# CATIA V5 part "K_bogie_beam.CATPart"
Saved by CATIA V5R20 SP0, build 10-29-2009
Part number: bogie_beam
Publications: "Droite.2", "Plan.3", "Corps principal", "Plan_pivot_bogie_tige", "Demi_bogie_beam"
Bounding box of the stored display mesh (mm): x -40 to 40, y -445.489 to 457.761, z -37.179 to 213.669
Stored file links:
  G:\Khaled_CFAO_2011\ST2M\ST2M_GR2\echouteau\Khaled\CAD_ThinkMotion\K_bogie_beam.CATPart
  F:\2A\Proj Think Motion\trainv3\Version3\sql_general.CATProduct
  G:\Khaled_CFAO_2011\ST2M\ST2M_GR2\echouteau\Khaled\CAD_ThinkMotion\K_tige.CATPart
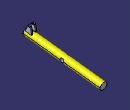
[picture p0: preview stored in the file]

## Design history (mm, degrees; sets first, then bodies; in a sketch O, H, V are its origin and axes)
Parameters
  Demi_bogie_beam = 400 mm
Set1
  Plane1 "plan_ref": linked copy from another document
  Point1: linked copy from another document
Body1 (main body)
  Point2: type OnPlane, Support Plane1, H 0, V 400 {= Demi_bogie_beam}, Direction (1, 0, 0)
  Point3: type OnPlane, Support Plane1, H 0, V -400 {= -Demi_bogie_beam}, Direction (1, 0, 0)
  Line1: type PtPt, FirstPoint Point2, SecondPoint Point3, Support Plane1
  Plane2: type OffsetPt, RefPlane Plane1, RefPoint Point3
  Plane3: type Offset, RefPlane Plane2, Offset 100
  Line2: type PtDir, RefPoint Point3, Direction Plane2, Start 0, End 100
  Plane4: type 1Line1Pt, RefPoint vertex of Line2, Line Line1
  Plane5 "Plan_pivot_bogie_tige": type OffsetPt, RefPlane Plane4, RefPoint Point3
  Plane6 "Plan_pivot_paire_roue": type Normal, Curve Line1, RefPoint Point3
  Line3: type PtDir, RefPoint Point1, Direction yz-plane, Start 0, End -157
  Plane7: type OffsetPt, RefPlane yz-plane, RefPoint vertex of Line3
  Line4: type PtDir, RefPoint vertex of Line2, Direction yz-plane, Start 0, End 150
  Plane8: type OffsetPt, RefPlane yz-plane, RefPoint vertex of Line4
  Line5 "Droite.qs": type Normal, RefPoint Point3, RefSkin Plane5, Start 0, End 250
  Line6 "Droite.qs": type Normal, RefPoint Point2, RefSkin Plane5, Start 0, End 250
  Plane9 "Plan.dec": type Offset, RefPlane Plane6, Offset 50
  Plane10: type OffsetPt, RefPlane Plane6, RefPoint Point2
  Plane11: type Offset, RefPlane Plane10, Offset 50, reversed
  Sketch1 on Plane9, origin (0, -452.9146, 0.1661), H (1, 0, 0), V (0, 0.1136, 0.9935)
    circle A1 centre (0, 105.2996) radius 40
    point P1 (0, 105.2996)
    reference projected point E1 (0, 105.2996) from Point2
    coincidence: P1 E1
  Pad1: profile Sketch1, direction (0, 0.9935, -0.1136), up to Plane11
  Plane12: stored without definition
  Plane13: stored without definition
  Point4: stored without definition
  Sketch2 on Plane13, origin (166, 16.1619, 44.1149), H (0, 1, 0), V (0, 0, 1)
    point P1 (-10.0259, 9.5353)
    reference projected point E1 (-10.0259, 9.5353) from Point4
    coincidence: P1 E1
  Hole1: placed by Sketch2, at (166, 6.136, 53.6503) direction (-1, 0, 0), diameter 45, up to Plane7
  Point5: stored without definition
  Line7: stored without definition
  Sketch3 on Plane9, origin (0, -447.0854, 51.1334), H (1, 0, 0), V (0, 0.1136, 0.9935)
    line L1 (29.6689, 171.2035) -> (29.6689, 80.2774)
    point P1 (29.6689, 171.2035)
    point P2 (29.6689, 80.2774)
    line L2 (29.6689, 80.2774) -> (0, 80.2774)
    point P3 (0, 80.2774)
    line L3 (29.6689, 171.2035) -> (16, 171.2035)
    point P4 (16, 171.2035)
    line L4 (16, 171.2035) -> (16, 92.17)
    point P5 (16, 92.17)
    line L5 (16, 92.17) -> (0, 92.17)
    point P6 (0, 92.17)
    point P7 (0, 80.2774)
    point P8 (-29.6689, 80.2774)
    line L6 (-29.6689, 80.2774) -> (0, 80.2774)
    point P9 (0, 92.17)
    point P10 (-16, 92.17)
    line L7 (-16, 92.17) -> (0, 92.17)
    point P11 (-16, 171.2035)
    line L8 (-16, 171.2035) -> (-16, 92.17)
    point P12 (-29.6689, 171.2035)
    line L9 (-29.6689, 171.2035) -> (-16, 171.2035)
    line L10 (-29.6689, 171.2035) -> (-29.6689, 80.2774)
    length L5 = 16
    vertical: L1 V, L4 V
    coincidence: P3 V, P6 V, P3 P7, P6 P9
    horizontal: L2 H, L3 H, L5 H
    symmetry: P3 P7 V, P2 P8 V, L2 L6 V, P6 P9 V, P5 P10 V, L5 L7 V, P4 P11 V, L4 L8 V, P1 P12 V, L3 L9 V, L1 L10 V
  Sketch4 on Plane5, origin (0, 0, 0), H (0, -1, 0), V (0, 0, 1)
    arc A1 centre (379.9103, 198.4545) radius 15.2266 from (393.8223, 204.6437) to (364.9601, 201.3427) ccw
    point P1 (379.9103, 198.4545)
    reference projected point E1 (379.9103, 198.4545) from Point5
    line L1 (393.8223, 204.6437) -> (428.336, 127.064)
    point P2 (393.8223, 204.6437)
    point P3 (428.336, 127.064)
    line L2 (428.336, 127.064) -> (388.5951, 122.5188)
    point P4 (388.5951, 122.5188)
    reference projected line E2 (-403.5453, 8.1983) -> (391.2733, 99.1022) from Line1
    reference projected line E3 (391.2733, 99.1022) -> (379.9103, 198.4545) from Line7
    reference intersected line E4 through (397.4093, 45.4519) direction (-0.1136, 0.9935) from Plane6
    point P7 (348.8542, 117.9736)
    point P8 (364.9601, 201.3427)
    line L3 (364.9601, 201.3427) -> (348.8542, 117.9736)
    point P9 (388.5951, 122.5188)
    line L4 (348.8542, 117.9736) -> (388.5951, 122.5188)
    length L2 = 40
    coincidence: P1 E1, P4 E3, P4 P9
    tangency: L1 A1
    parallelism: L2 E2
    symmetry: P3 P7 E4, P2 P8 E4, L1 L3 E4, P4 P9 E4, L2 L4 E4
  SolidCombine1: FirstComponentProfile Sketch3, FirstComponentDirection Sketch3, SecondComponentProfile Sketch4, SecondComponentDirection Sketch4
  Sketch5 on face of SolidCombine1 from Sketch3.L1, origin (29.6689, -375.822, 206.9149), H (0, 1, 0), V (0, 0, 1)
    point P1 (-4.0883, -8.4604)
    reference projected arc E1 centre (-4.0883, -8.4604) radius 15.2266 from (10.7446, -5.0199) to (-17.7613, -1.7597) ccw from edge [face of SolidCombine1 from Sketch3.L1 | face of SolidCombine1 from Sketch4.A1]
    concentricity: P1 E1
  Hole2: placed by Sketch5, at (29.6689, -379.9103, 198.4545) direction (-1, 0, 0), diameter 15, up to face of SolidCombine1 from Sketch3.L10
